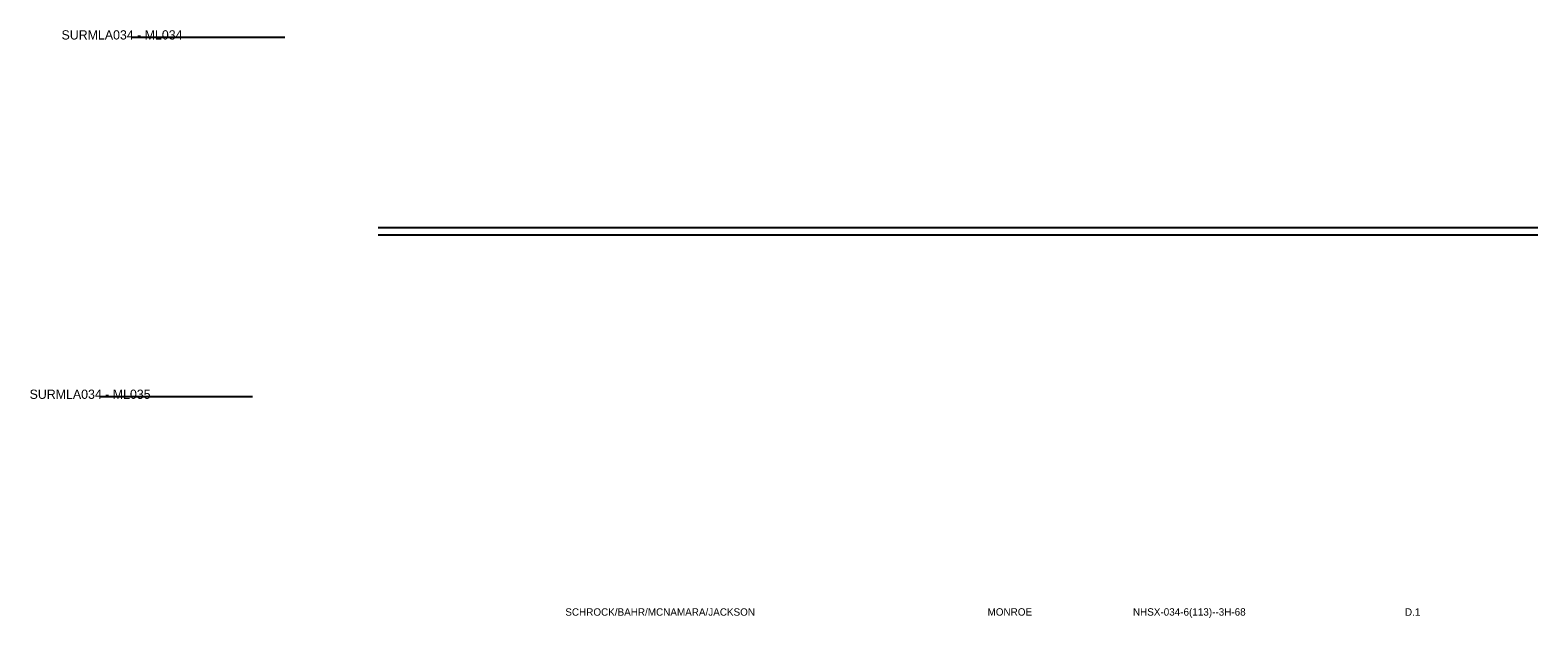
# Model space of a CAD drawing. Extents: x -0.67 to 2.72, y 0.07 to 1.4.
import ezdxf

# ---------------------------------------------------------------- set-up
doc = ezdxf.new("R2010")
doc.units = 0
doc.layers.add('dsnCellElements', color=7, linetype='Continuous')
doc.layers.add('TextNonPlot', color=7, linetype='Continuous')

msp = doc.modelspace()

# ---------------------------------------------------------------- linework, layer by layer
at = {"layer": 'dsnCellElements'}
for p, q in [((0.1104, 0.9533), (2.7229, 0.9533)), ((0.1104, 0.9367), (2.7229, 0.9367))]:
    msp.add_line(p, q, dxfattribs=at)
at = {"layer": 'TextNonPlot'}
for p, q in [((-0.4437, 1.3821), (-0.0995, 1.3821)), ((-0.516, 0.5723), (-0.1726, 0.5723))]:
    msp.add_line(p, q, dxfattribs=at)

# ---------------------------------------------------------------- texts
for s, height, p in [('SURMLA034 - ML034', 0.020833, (-0.6027, 1.3768)), ('SURMLA034 - ML035', 0.020833, (-0.6746, 0.567)), ('SCHROCK/BAHR/MCNAMARA/JACKSON', 0.016667, (0.5322, 0.0783)), ('MONROE', 0.01667, (1.4833, 0.0785)), ('NHSX-034-6(113)--3H-68', 0.016667, (1.8108, 0.0785)), ('D.1', 0.01667, (2.4236, 0.0783))]:
    msp.add_text(s, height=height, dxfattribs=at).set_placement(p)

doc.saveas('drawing.dxf')
